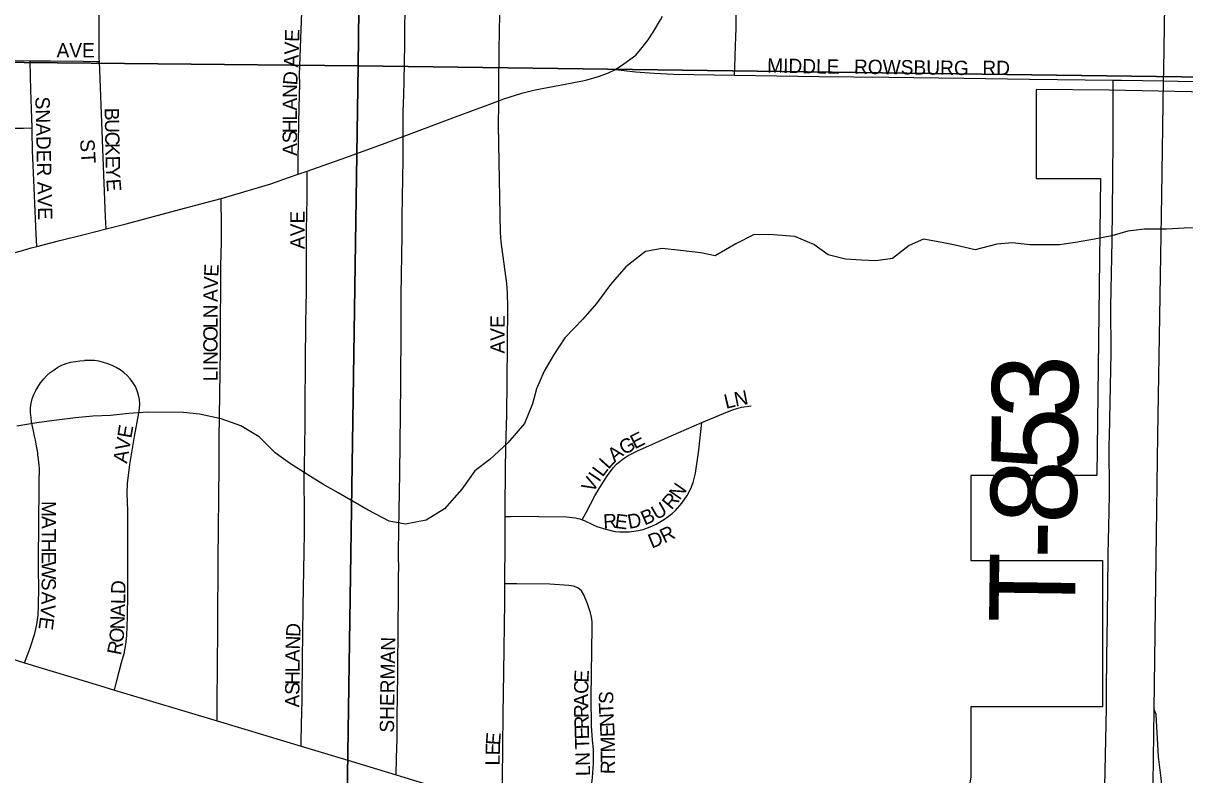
# Model space of a CAD drawing. Extents: x 1874609 to 2204689, y 815661 to 1281160.
# Drawn here: x 2023217 to 2027275, y 1043918 to 1046543 of the extents above; entities that cross this region are included whole.
import ezdxf

# ---------------------------------------------------------------- set-up
doc = ezdxf.new("R2010")
doc.units = 0
for name, color, linetype in [('GM_X_City_Street', 7, 'Continuous'), ('GM_X_City_Street_Text', 7, 'Continuous'), ('GM_X_Corporation', 7, 'Continuous'), ('GM_X_County_Road', 7, 'Continuous'), ('GM_X_Interchange_Ramps', 7, 'Continuous'), ('GM_X_Minor_River', 7, 'Continuous'), ('GM_X_Section', 7, 'Continuous'), ('GM_X_State_Route', 7, 'Continuous'), ('GM_X_Township_Road', 7, 'Continuous'), ('GM_X_Township_Road_Text', 7, 'Continuous'), ('GM_X_US_Route', 7, 'Continuous')]:
    doc.layers.add(name, color=color, linetype=linetype)

msp = doc.modelspace()

# ---------------------------------------------------------------- linework, layer by layer
at = {"layer": 'GM_X_City_Street'}
for points in [[(2023483, 1046409.1), (2023482.6, 1046420.9), (2023481.8, 1046583.7), (2023481.7, 1046592.4)], [(2024177.5, 1046015.3), (2024177.7, 1046037.7), (2024178, 1046069.3), (2024180.5, 1046249.6), (2024183.1, 1046330.7), (2024182.7, 1046363.2), (2024186.9, 1046488.7), (2024189.4, 1046550.8), (2024190.6, 1046580.3)], [(2024544.5, 1046147.1), (2024544.5, 1046147.5), (2024544.5, 1046196.5), (2024544.6, 1046235.1), (2024546.5, 1046292.2), (2024547.5, 1046340.1), (2024549.8, 1046470.2), (2024550.2, 1046535.3), (2024550.9, 1046576.9)], [(2024878.2, 1046271.7), (2024878.3, 1046322.2), (2024880.2, 1046452.3), (2024882.2, 1046574)], [(2025285.5, 1046381.4), (2025314.8, 1046400.7), (2025335.7, 1046415.7), (2025357.2, 1046431.7), (2025379.1, 1046458.6), (2025399.7, 1046484.6), (2025418.2, 1046511.9), (2025443.1, 1046554.5), (2025450.2, 1046568.1)], [(2025701.7, 1046361.9), (2025702.6, 1046388.8), (2025704, 1046427.4), (2025705.3, 1046462.4), (2025706.5, 1046495.1), (2025707.6, 1046524.4), (2025707.6, 1046558.4), (2025707.7, 1046598.6)], [(2022983.9, 1046415), (2022987.2, 1046414.9), (2023051.7, 1046414.4), (2023099.2, 1046413.5), (2023241.8, 1046412.1)], [(2023241.8, 1046412.1), (2023312.4, 1046411.5), (2023426.7, 1046410), (2023474.3, 1046409.3), (2023483, 1046409.1)], [(2023248.3, 1046177), (2023246.3, 1046244.1), (2023244.1, 1046309.1), (2023243, 1046357.8), (2023241.8, 1046412.1)], [(2023506.3, 1045824.7), (2023504.5, 1045867.2), (2023498.4, 1046013.8), (2023489, 1046258), (2023483, 1046409.1)], [(2024878.2, 1046271.7), (2024896.4, 1046278.4), (2024958.4, 1046298.6), (2025005.7, 1046310.4), (2025134.2, 1046334.6), (2025182.3, 1046344.6), (2025230, 1046357.8), (2025261.2, 1046369.7), (2025285.5, 1046381.4)], [(2025285.5, 1046381.4), (2025355.8, 1046373), (2025421, 1046368), (2025488.7, 1046365.2), (2025701.7, 1046361.9)], [(2025701.7, 1046361.9), (2025995.8, 1046357.2), (2026241.2, 1046354.9), (2026502.9, 1046351.4), (2026731.9, 1046348)], [(2024544.5, 1046147.1), (2024727.2, 1046215.8), (2024878.2, 1046271.7)], [(2024901, 1044820.1), (2024901.1, 1044849.9), (2024901.7, 1044981.2), (2024902.4, 1045062.5), (2024906, 1045175.3), (2024908.2, 1045293.1), (2024909, 1045421.5), (2024910, 1045552.4), (2024909.3, 1045601.5), (2024906.6, 1045633.8), (2024886.7, 1045779.4), (2024884.6, 1045812.2), (2024880.1, 1046059), (2024877.4, 1046188.6), (2024878.1, 1046263), (2024878.2, 1046271.7)], [(2022985.8, 1046176.9), (2023039.3, 1046177.1), (2023186, 1046176.5), (2023218.4, 1046176.7), (2023248.3, 1046177)], [(2023264.3, 1045763.3), (2023262.4, 1045805.5), (2023258.7, 1045886.4), (2023255.2, 1045967.6), (2023249.7, 1046098), (2023248.7, 1046163.1), (2023248.3, 1046177)], [(2024209.4, 1046026.5), (2024343.5, 1046073.7), (2024481.4, 1046123.4), (2024544.5, 1046147.1)], [(2024519.9, 1043917), (2024521.5, 1043976.9), (2024523, 1044042.5), (2024523.6, 1044124), (2024524.2, 1044188.2), (2024526, 1044273.7), (2024526.2, 1044334.1), (2024526.4, 1044383.1), (2024526.5, 1044415.3), (2024527.2, 1044464.7), (2024527.9, 1044512.4), (2024528.1, 1044594.3), (2024528.6, 1044610.7), (2024528.7, 1044643.6), (2024528.5, 1044675.7), (2024528.4, 1044692.2), (2024528.3, 1044708.6), (2024529.3, 1044757.6), (2024529.3, 1044774), (2024530.1, 1044839.5), (2024532.1, 1044970.9), (2024536.1, 1045282.5), (2024537, 1045479.1), (2024537.6, 1045594), (2024540.5, 1045801.8), (2024540.4, 1045867.2), (2024543.1, 1046001.4), (2024543.8, 1046065.9), (2024544.5, 1046147.1)], [(2023908, 1045931.2), (2023956.4, 1045944.6), (2024082, 1045982.4), (2024144, 1046003.5), (2024177.5, 1046015.3)], [(2024177.5, 1046015.3), (2024209.4, 1046026.5)], [(2024187.8, 1044017.7), (2024188.1, 1044029.8), (2024189.3, 1044094.3), (2024191.7, 1044176.8), (2024192.2, 1044324.9), (2024193.9, 1044407.1), (2024195.5, 1044505.9), (2024198.7, 1044696.2), (2024199.2, 1044761.8), (2024199.2, 1044826.6), (2024199.3, 1044859.4), (2024198.7, 1044925.1), (2024198.7, 1044957.9), (2024199.4, 1044989.4), (2024201.3, 1045071.3), (2024202.3, 1045136.4), (2024202.3, 1045266.2), (2024202.8, 1045298.9), (2024203.3, 1045331.5), (2024203, 1045347.9), (2024203.2, 1045362), (2024203.2, 1045394.8), (2024204, 1045459.1), (2024204.5, 1045489.8), (2024204.6, 1045506.4), (2024205, 1045539.1), (2024206.2, 1045619.8), (2024207.1, 1045751.1), (2024207.1, 1045830), (2024208, 1045862.6), (2024208.4, 1045944.7), (2024209.3, 1046016.3), (2024209.4, 1046026.5)], [(2023506.3, 1045824.7), (2023576.7, 1045842.4), (2023798.4, 1045901.1), (2023908, 1045931.2)], [(2023894.2, 1044105.9), (2023894.3, 1044119.2), (2023894.9, 1044186), (2023896.1, 1044280.4), (2023897.2, 1044443.4), (2023898.4, 1044669.7), (2023901.6, 1044995.8), (2023902.1, 1045093.8), (2023904.8, 1045323), (2023906.5, 1045404.8), (2023906.7, 1045519.3), (2023907.3, 1045606), (2023907.8, 1045694), (2023909.2, 1045779.6), (2023909.2, 1045851.6), (2023908.3, 1045913.6), (2023908, 1045931.2)], [(2023264.3, 1045763.3), (2023339.9, 1045783), (2023434.4, 1045806.6), (2023506.3, 1045824.7)], [(2022856.4, 1045656.7), (2022868.1, 1045659.5), (2022947.6, 1045679.1), (2023011, 1045695.1), (2023094.2, 1045715.5), (2023168, 1045735.7), (2023214.4, 1045749.3), (2023245.3, 1045758.4), (2023264.3, 1045763.3)], [(2023272.7, 1044939.4), (2023273.4, 1044987.1), (2023272.3, 1044998.9), (2023270.6, 1045018.7), (2023268.6, 1045034.9), (2023267.7, 1045041.3), (2023266.4, 1045049.6), (2023264.6, 1045060.8), (2023262.5, 1045072.1), (2023259.7, 1045086), (2023256.9, 1045100.2), (2023252.7, 1045118.5), (2023250, 1045133.9), (2023246.3, 1045150.7), (2023244.4, 1045164.6), (2023242.7, 1045183.1), (2023242.6, 1045199.2), (2023244.5, 1045215.1), (2023248.2, 1045230.7), (2023253.7, 1045245.7), (2023260.9, 1045260.2), (2023267.7, 1045271.5), (2023277.7, 1045287), (2023288.5, 1045300.8), (2023299.4, 1045312.7), (2023311.3, 1045323.1), (2023324.8, 1045332.5), (2023338.3, 1045341.3), (2023352.5, 1045348.5), (2023367.5, 1045354.2), (2023382.5, 1045358.4), (2023399.2, 1045361.7), (2023415.3, 1045364), (2023431.3, 1045365)], [(2023582.2, 1044839.4), (2023580.2, 1044901.7), (2023581.5, 1044935), (2023589.9, 1045001), (2023606, 1045099.1), (2023620.7, 1045180.5), (2023623, 1045196.6), (2023624, 1045212.6), (2023623.2, 1045228.5), (2023620.3, 1045244.1), (2023615.5, 1045259.2), (2023608.8, 1045273.7), (2023600.4, 1045287.3), (2023590.5, 1045300.2), (2023580.6, 1045311.8), (2023569, 1045322.3), (2023555.9, 1045331.6), (2023542, 1045340), (2023527.5, 1045347.3), (2023512.7, 1045353.4), (2023497.3, 1045358.3), (2023481.6, 1045362), (2023465.6, 1045364.2), (2023445.7, 1045364.9), (2023431.3, 1045365)], [(2025587.8, 1045147.6), (2025663.4, 1045180.1), (2025694.4, 1045192.1), (2025710.3, 1045197.3), (2025726.6, 1045201.3), (2025759.8, 1045206.2)], [(2025169.1, 1044808.3), (2025183.1, 1044834.3), (2025214.3, 1044892.5), (2025231.3, 1044921.1), (2025258.1, 1044963.2), (2025278.3, 1044990.1), (2025289.9, 1045002.5), (2025302.8, 1045013.5), (2025316.4, 1045023.5), (2025330.7, 1045032.4), (2025360.4, 1045047.7), (2025481.1, 1045101.7), (2025587.8, 1045147.6)], [(2025169.1, 1044808.3), (2025176.6, 1044805.5), (2025205.8, 1044791.7), (2025221.4, 1044785.3), (2025252.7, 1044775.2), (2025284.3, 1044767.9), (2025301, 1044766.4), (2025317.4, 1044766), (2025334, 1044766.4), (2025350.4, 1044768), (2025366.6, 1044770.6), (2025382.6, 1044774.5), (2025398.1, 1044779.7), (2025413.4, 1044786.1), (2025428.2, 1044793.5), (2025456.8, 1044810), (2025470.5, 1044819.4), (2025483.5, 1044829.7), (2025495.7, 1044841.2), (2025517.3, 1044866.2), (2025536.1, 1044893.4), (2025544.2, 1044907.9), (2025551.2, 1044923.1), (2025556.9, 1044938.8), (2025565, 1044970.8), (2025577.3, 1045051.6), (2025584.4, 1045116.5), (2025587.8, 1045147.6)], [(2023222.1, 1044309), (2023236.7, 1044348.6), (2023242.3, 1044364), (2023257.6, 1044410.9), (2023264.9, 1044442.8), (2023269.4, 1044474.9), (2023271, 1044507.6), (2023271.2, 1044573.1), (2023271, 1044631.5), (2023270.8, 1044687.3), (2023271, 1044713.9), (2023271.2, 1044747.9), (2023271.5, 1044783.5), (2023271.8, 1044816.8), (2023272, 1044849.3), (2023272.2, 1044869.1), (2023272.5, 1044911.9), (2023272.7, 1044939.4)], [(2023535.8, 1044213.5), (2023544.4, 1044246.5), (2023560.9, 1044309.8), (2023569.3, 1044341.1), (2023575.3, 1044372.6), (2023579, 1044404.5), (2023581.5, 1044469.2), (2023582.5, 1044549.6), (2023582.6, 1044581.4), (2023582.9, 1044644.9), (2023582.9, 1044693.3), (2023582, 1044823.2), (2023582.2, 1044839.4)], [(2024899.4, 1044584.7), (2024900.6, 1044734.7), (2024901, 1044820.1)], [(2024901, 1044820.1), (2024920.5, 1044820.3), (2024971.6, 1044820.6), (2025018.2, 1044819.6), (2025115.3, 1044818.7), (2025146.6, 1044814.9), (2025161.7, 1044811.1), (2025169.1, 1044808.3)], [(2024891.4, 1043805.5), (2024891.4, 1043814.6), (2024891.6, 1043901.1), (2024892.7, 1044015.4), (2024893.9, 1044129.2), (2024896.3, 1044275.2), (2024898.9, 1044521.7), (2024899.4, 1044584.7)], [(2025183, 1043716.8), (2025188.2, 1043759.9), (2025206, 1043907.4), (2025208.9, 1043956.8), (2025208.9, 1044006.2), (2025206.1, 1044038), (2025202.4, 1044088.3), (2025201, 1044187.2), (2025205.1, 1044434.8), (2025204.6, 1044451.3), (2025202.3, 1044467.6), (2025198.3, 1044483.6), (2025187.7, 1044514.9), (2025175.5, 1044545.7), (2025166.9, 1044559.8), (2025154.7, 1044570.3), (2025139.5, 1044576.2), (2025123.2, 1044578.8), (2025057.2, 1044583.6), (2024941.7, 1044584.4), (2024917.7, 1044584.6), (2024899.4, 1044584.7)]]:
    msp.add_lwpolyline(points, dxfattribs=at)
at = {"layer": 'GM_X_Corporation'}
msp.add_lwpolyline([(2028503.5, 1046278.8), (2027010.4, 1046309.5), (2026755.9, 1046311.2), (2026755.9, 1046000.1), (2026979.9, 1046000), (2026967.6, 1044962.5), (2026527.5, 1044962.5), (2026527.5, 1044666.4), (2026987.6, 1044666.4), (2026987.6, 1044155.2), (2026527.4, 1044155.2), (2026527.4, 1043909.1), (2026495.6, 1043728.8), (2026985.8, 1043728.8), (2026985.8, 1043511.5), (2027343.9, 1043511.5)], dxfattribs=at)
at = {"layer": 'GM_X_County_Road'}
for points in [[(2026731.9, 1046348), (2027024.9, 1046344.5)], [(2027024.9, 1046344.5), (2027053.9, 1046344), (2027200.9, 1046341.3)], [(2027200.9, 1046341.3), (2027251.3, 1046340.4), (2027382.9, 1046339), (2027613.2, 1046335.2), (2027860.1, 1046330.8), (2028189.3, 1046324.6), (2028337.4, 1046322.9), (2028492.5, 1046319.8)]]:
    msp.add_lwpolyline(points, dxfattribs=at)
at = {"layer": 'GM_X_Interchange_Ramps'}
msp.add_lwpolyline([(2027333.5, 1043611.9), (2027266.8, 1043674.5), (2027255.8, 1043686.8), (2027245.6, 1043699.8), (2027236.4, 1043713.5), (2027228.2, 1043727.8), (2027221, 1043742.5), (2027214.8, 1043757.8), (2027209.7, 1043773.4), (2027203.7, 1043799.7), (2027202.4, 1043805.5), (2027198, 1043838.3), (2027191.9, 1043905.8), (2027183.1, 1043979.6), (2027174.2, 1044127.6), (2027172.9, 1044133.6), (2027168, 1044145.6)], dxfattribs=at)
at = {"layer": 'GM_X_Minor_River'}
msp.add_lwpolyline([(2027353, 1045829.1), (2027272.7, 1045827.3), (2027210.5, 1045823.5), (2027134.3, 1045823.8), (2027076.1, 1045816), (2027019.9, 1045800.1), (2026959.7, 1045788.3), (2026893.5, 1045776.5), (2026837.3, 1045768.7), (2026733, 1045769), (2026672.8, 1045775.3), (2026618.7, 1045771.4), (2026542.4, 1045751.6), (2026472.2, 1045767.9), (2026420.1, 1045778.2), (2026362, 1045788.4), (2026311.8, 1045766.5), (2026253.5, 1045720.5), (2026195.3, 1045712.7), (2026145.1, 1045714.9), (2026089, 1045719.1), (2026028.9, 1045733.4), (2025978.8, 1045769.7), (2025912.7, 1045798), (2025838.5, 1045804.3), (2025770.3, 1045804.5), (2025706, 1045772.6), (2025633.7, 1045730.7), (2025583.6, 1045740.9), (2025513.4, 1045749.2), (2025449.2, 1045755.5), (2025391, 1045745.6), (2025322.7, 1045691.7), (2025268.4, 1045629.7), (2025220, 1045563.6), (2025171.7, 1045509.6), (2025109.4, 1045443.6), (2025069.1, 1045383.6), (2025036.8, 1045327.5), (2025010.6, 1045265.4), (2024996.4, 1045213.2), (2024968.1, 1045145.1), (2024909.7, 1045077.1), (2024847.4, 1045019.1), (2024795.1, 1044979.2), (2024748.8, 1044915.1), (2024688.4, 1044847.1), (2024624.1, 1044807.2), (2024551.9, 1044793.4), (2024495.7, 1044803.7), (2024421.6, 1044842), (2024317.5, 1044902.6), (2024263.4, 1044932.9), (2024211.4, 1044965.2), (2024147.3, 1045005.5), (2024097.3, 1045041.8), (2024041.2, 1045098.2), (2023977.2, 1045136.5), (2023909, 1045160.9), (2023832.9, 1045177.2), (2023776.7, 1045183.4), (2023652.4, 1045183.8), (2023586.1, 1045180), (2023521.9, 1045172.2), (2023459.7, 1045170.5), (2023399.6, 1045164.6), (2023325.3, 1045154.9), (2023265.1, 1045147), (2023194.9, 1045135.3)], dxfattribs=at)
at = {"layer": 'GM_X_Section'}
for points in [[(2024449.5, 1051689), (2024387.7, 1046393.6), (2019020.7, 1046448.2), (2019058.5, 1051739.8)], [(2029754.6, 1051618), (2029702.7, 1046322.8), (2024387.7, 1046393.6), (2024449.5, 1051689)], [(2024387.7, 1046393.6), (2024307, 1041050.6), (2018988, 1041097.3), (2019020.7, 1046448.2)], [(2029702.7, 1046322.8), (2029613.9, 1041007.7), (2024307, 1041050.6), (2024387.7, 1046393.6)]]:
    msp.add_lwpolyline(points, close=True, dxfattribs=at)
at = {"layer": 'GM_X_State_Route'}
for points in [[(2023095.5, 1044347.8), (2023222.1, 1044309), (2023483, 1044229.3), (2023535.8, 1044213.5), (2023657, 1044177.1)], [(2023657, 1044177.1), (2023781.6, 1044139.7), (2023894.2, 1044105.9), (2024064.4, 1044054.8), (2024187.8, 1044017.7), (2024362.9, 1043965.1), (2024519.9, 1043917), (2024534.6, 1043912.5), (2024691.6, 1043865.2), (2024864.4, 1043813.7), (2024891.4, 1043805.5), (2025183, 1043716.8), (2025204.3, 1043710.4), (2025239.7, 1043699.6)]]:
    msp.add_lwpolyline(points, dxfattribs=at)
at = {"layer": 'GM_X_Township_Road'}
for points in [[(2027023.1, 1045998.9), (2027024.4, 1046143.6), (2027024, 1046244.2), (2027024.9, 1046344.5)], [(2027011.1, 1045075), (2027011.5, 1045096.2), (2027012.4, 1045161.5), (2027017.3, 1045390.3), (2027016.8, 1045553.8), (2027021.1, 1045782.8), (2027023.1, 1045998.9)], [(2027010.1, 1044820.6), (2027010, 1044825.5), (2027010.3, 1044838.4), (2027011.5, 1044896.2), (2027011.1, 1045075)], [(2027001.5, 1044217.9), (2027001.7, 1044225.4), (2027002.8, 1044313.1), (2027004, 1044414), (2027004.5, 1044455.5), (2027006.1, 1044592.9), (2027006.8, 1044659), (2027007.4, 1044689.6), (2027008.3, 1044735.6), (2027009.4, 1044785.8), (2027009.7, 1044802.1), (2027010.1, 1044820.6)], [(2026995.5, 1043852.6), (2026995.5, 1043856.9), (2026995.8, 1043876.8), (2027000.8, 1044149.6), (2027001.5, 1044217.9)]]:
    msp.add_lwpolyline(points, dxfattribs=at)
at = {"layer": 'GM_X_US_Route'}
for points in [[(2027200.9, 1046341.3), (2027201.5, 1046380.7), (2027204.5, 1046605.8), (2027210.8, 1047112.7), (2027216.4, 1047439.1)], [(2027163.4, 1043800.7), (2027168, 1044145.6), (2027176.3, 1044758.9), (2027180.6, 1045103.7), (2027186.5, 1045448.4), (2027189.7, 1045661.9), (2027194.3, 1045941.1), (2027200.9, 1046341.3)]]:
    msp.add_lwpolyline(points, dxfattribs=at)

# ---------------------------------------------------------------- texts
at = {"layer": 'GM_X_City_Street_Text'}
for s, rotation, p in [('AVE', 88.0261, (2024177.7, 1046388)), ('AVE', 0, (2023333.5, 1046423.5)), ('MIDDLE', 358.9565, (2025815.5, 1046370.7)), ('ROWSBURG', 359.3562, (2026118.8, 1046366.3)), ('RD', 0, (2026567.5, 1046361.9)), ('D', 85.142, (2024173.9, 1046325)), ('N', 89.3879, (2024173.4, 1046282)), ('SNADER AVE', 271.3012, (2023259.4, 1046286.2)), ('A', 89.9703, (2024173.4, 1046238.1)), ('B', 271.0928, (2023501.4, 1046247.1)), ('U', 271.1196, (2023502.1, 1046207.4)), ('L', 89.9707, (2024173.4, 1046202.9)), ('H', 89.9563, (2024173.4, 1046158.9)), ('S', 89.9727, (2024173.3, 1046123.7)), ('ST', 273.5746, (2023415.5, 1046136.5)), ('C', 271.0928, (2023503, 1046163.5)), ('A', 89.9781, (2024173.3, 1046079.7)), ('K', 271.0929, (2023503.7, 1046123.9)), ('E', 271.1246, (2023504.6, 1046079.8)), ('Y', 272.2474, (2023505.3, 1046043.6)), ('E', 274.2185, (2023507.1, 1045997.7)), ('AVE', 90, (2024199.7, 1045754.1)), ('E', 87.4036, (2023898.5, 1045656.7)), ('V', 87.6605, (2023896.7, 1045612.8)), ('A', 89.3442, (2023896.2, 1045569.2)), ('N', 89.9781, (2023896.2, 1045512.1)), ('L', 89.9956, (2023896.2, 1045477)), ('AVE', 90, (2024899.3, 1045388.9)), ('O', 89.9812, (2023896.2, 1045432.9)), ('C', 89.9757, (2023896.1, 1045393.3)), ('N', 89.9928, (2023896.1, 1045349.3)), ('I', 89.9563, (2023896.1, 1045327.3)), ('L', 90, (2023896.1, 1045292.1)), ('L', 13.4267, (2025671.9, 1045195.6)), ('N', 11.0828, (2025705.6, 1045203.6)), ('AVE', 80.2226, (2023579.5, 1045003.3)), ('E', 26.785, (2025353.7, 1045054.2)), ('G', 28.7552, (2025315.5, 1045033.2)), ('A', 39.0695, (2025283.3, 1045006.8)), ('L', 53.376, (2025240.8, 1044955)), ('L', 47.4543, (2025260.9, 1044982.2)), ('V', 60.9411, (2025208.1, 1044899.8)), ('I', 55.8855, (2025228.8, 1044937.3)), ('N', 55.2021, (2025510.3, 1044874.5)), ('M', 269.9636, (2023281.3, 1044874.1)), ('U', 29.6698, (2025429.2, 1044806.3)), ('R', 50.072, (2025482, 1044840.3)), ('R', 3.7188, (2025244.6, 1044777.3)), ('E', 353.0444, (2025281.7, 1044780)), ('D', 10.4736, (2025332.9, 1044776.2)), ('B', 23.8505, (2025388.1, 1044787.9)), ('A', 269.9812, (2023281.3, 1044821.3)), ('R', 25.7909, (2025456.2, 1044725.4)), ('T', 269.9727, (2023281.3, 1044777.3)), ('D', 22.5442, (2025412.8, 1044707.3)), ('H', 269.9703, (2023281.3, 1044742.1)), ('E', 269.9707, (2023281.3, 1044698.1)), ('W', 269.9664, (2023281.2, 1044662.9)), ('S', 269.9707, (2023281.2, 1044605.7)), ('D', 88.7323, (2023573.8, 1044548.3)), ('A', 269.2349, (2023281.2, 1044557.5)), ('L', 88.7377, (2023573, 1044513.1)), ('V', 264.1763, (2023280.7, 1044514.6)), ('A', 88.7204, (2023572, 1044469.1)), ('E', 262.2988, (2023276.3, 1044471.3)), ('N', 88.3489, (2023570.7, 1044424.7)), ('O', 84.9248, (2023566.6, 1044377.6)), ('D', 87.8874, (2024184.9, 1044398.4)), ('R', 78.9282, (2023558.2, 1044333.1)), ('N', 87.8797, (2024183.3, 1044354.4)), ('SHERMAN', 89.1712, (2024512.1, 1044064.3)), ('A', 88.6449, (2024182.2, 1044310.6)), ('L', 89.8907, (2024182.2, 1044275.7)), ('H', 89.9928, (2024182.2, 1044231.7)), ('E', 87.8142, (2025191.7, 1044238.7)), ('S', 89.9727, (2024182.1, 1044196.5)), ('C', 88.1054, (2025190.4, 1044199.2)), ('A', 89.9781, (2024182.1, 1044152.5)), ('A', 90.5028, (2025190.8, 1044155.8)), ('S', 88.0599, (2025277.6, 1044164)), ('R', 91.7631, (2025192, 1044116.5)), ('T', 92.7601, (2025279.3, 1044129.9)), ('R', 91.7631, (2025193.2, 1044076.9)), ('N', 93.2749, (2025281.8, 1044086.1)), ('E', 92.6535, (2025283.5, 1044050.4)), ('E', 85.7061, (2024882.6, 1044019.5)), ('E', 91.7641, (2025194.3, 1044041.7)), ('E', 88.716, (2024881.8, 1043985)), ('T', 91.7641, (2025195.4, 1044006.5)), ('M', 91.0236, (2025284.5, 1043996)), ('L', 89.8634, (2024881.7, 1043950.1)), ('N', 91.7397, (2025197.2, 1043949.3)), ('T', 89.9707, (2025284.5, 1043959.8)), ('L', 90.6733, (2025197.6, 1043913.1)), ('R', 88.8419, (2025283.6, 1043919.2))]:
    msp.add_text(s, height=50, rotation=rotation, dxfattribs=at).set_placement(p)
at = {"layer": 'GM_X_Township_Road_Text'}
for s, rotation, p in [('3', 89.336, (2026900.5, 1045160)), ('5', 89.3099, (2026898.3, 1044976.5)), ('8', 89.1586, (2026895.6, 1044792.3)), ('-', 89.1501, (2026893.7, 1044670.2)), ('T', 89.196, (2026890.6, 1044446.3))]:
    msp.add_text(s, height=300, rotation=rotation, dxfattribs=at).set_placement(p)

doc.saveas('drawing.dxf')
